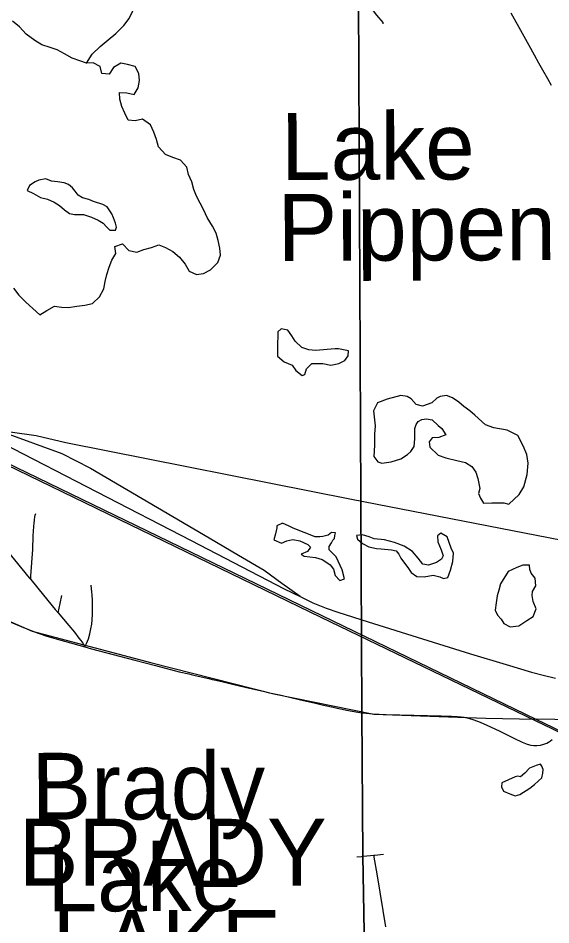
# Model space of a CAD drawing. Extents: x 0 to 34, y 0 to 22.
# Drawn here: x 4.548 to 5.303, y 14.669 to 15.953 of the extents above; entities that cross this region are included whole.
import ezdxf

# ---------------------------------------------------------------- set-up
doc = ezdxf.new("R2010")
doc.units = 0
for name, color, linetype in [('GM_X_Corporation', 7, 'Continuous'), ('GM_X_Corporation_Text', 7, 'Continuous'), ('GM_X_County_Road', 7, 'Continuous'), ('GM_X_Major_Lake', 7, 'Continuous'), ('GM_X_Major_Lake_Text', 7, 'Continuous'), ('GM_X_Minor_Lake', 7, 'Continuous'), ('GM_X_Minor_River', 7, 'Continuous'), ('GM_X_Rail_Line', 7, 'Continuous'), ('GM_X_Township_Road', 7, 'Continuous')]:
    doc.layers.add(name, color=color, linetype=linetype)

msp = doc.modelspace()

# ---------------------------------------------------------------- linework, layer by layer
at = {"layer": 'GM_X_Corporation'}
for points in [[(2.1, 14.1), (5.0398, 14.1), (5.0411, 14.425), (5.0381, 14.4922), (5.0378, 14.5635), (5.0395, 14.6051), (5.0366, 14.7668), (5.0353, 14.97), (5.0288, 16.3849), (5.0258, 16.7286), (5.0235, 17.4989), (5.0235, 17.5004), (5.0224, 17.5004), (4.9697, 17.5009), (4.8689, 17.5017), (4.8462, 17.5018), (4.8313, 17.5017), (4.8033, 17.5014), (4.7857, 17.5004), (4.7764, 17.4996), (4.7708, 17.4988), (4.7665, 17.4977), (4.718, 17.4962), (3.7119, 17.4934)], [(5.0288, 16.3849), (5.0353, 14.97), (5.0366, 14.7668), (5.0395, 14.6051), (5.0378, 14.5635), (5.0381, 14.4922), (5.0411, 14.425), (5.0398, 14.1), (8.9, 14.1)]]:
    msp.add_lwpolyline(points, dxfattribs=at)
at = {"layer": 'GM_X_County_Road'}
for points in [[(5.3042, 15.858), (5.2988, 15.8674), (5.2917, 15.8798), (5.2862, 15.8895), (5.28, 15.901), (5.2725, 15.9146), (5.2632, 15.9313), (5.247, 15.9603)], [(4.4651, 15.2783), (4.4794, 15.2608), (4.4944, 15.2435), (4.5133, 15.2212), (4.5219, 15.2114), (4.5641, 15.1605), (4.5661, 15.158)], [(4.5661, 15.158), (4.584, 15.1358), (4.6008, 15.1158), (4.605, 15.1108)], [(4.605, 15.1108), (4.6199, 15.0929), (4.6281, 15.0835), (4.6344, 15.0753), (4.6372, 15.0718), (4.6386, 15.0698), (4.6398, 15.0679), (4.6426, 15.0628)], [(4.5348, 15.0992), (4.5469, 15.0939), (4.5584, 15.0892), (4.5667, 15.086), (4.5701, 15.0846), (4.589, 15.078), (4.6056, 15.073), (4.6426, 15.0628)], [(4.6426, 15.0628), (4.6523, 15.0601), (4.7136, 15.0439), (4.7431, 15.0363), (4.7767, 15.0275), (4.79, 15.0244), (4.7936, 15.0236), (4.799, 15.0223), (4.8183, 15.0178), (4.8231, 15.0167), (4.8261, 15.0159), (4.8369, 15.0135), (4.8538, 15.0096), (4.8763, 15.0045), (4.8956, 14.9999), (4.9047, 14.9978), (4.9211, 14.9942), (4.9465, 14.9884), (4.9695, 14.9831), (4.981, 14.9804), (4.9949, 14.9773), (5.0003, 14.9761), (5.0076, 14.9746), (5.0137, 14.9733), (5.0295, 14.9703), (5.0355, 14.9694)], [(5.0355, 14.9694), (5.0374, 14.9692), (5.0504, 14.968), (5.0699, 14.9671), (5.1088, 14.9662), (5.1479, 14.9651), (5.1622, 14.9648), (5.171, 14.9642), (5.1761, 14.9636), (5.1802, 14.963), (5.1864, 14.9617), (5.1942, 14.9594), (5.203, 14.956), (5.2127, 14.9518), (5.224, 14.9466), (5.2307, 14.9433), (5.2507, 14.9333), (5.2625, 14.9277), (5.2694, 14.9251), (5.2747, 14.9237), (5.2789, 14.9232), (5.2831, 14.9231), (5.2885, 14.9236), (5.2932, 14.9248), (5.2977, 14.9266), (5.2999, 14.9277), (5.3027, 14.9295), (5.3052, 14.9316)]]:
    msp.add_lwpolyline(points, dxfattribs=at)
at = {"layer": 'GM_X_Major_Lake'}
msp.add_line((4.6134, 15.72), (4.6039, 15.7214), dxfattribs=at)
for points in [[(4.801, 15.5902), (4.8108, 15.5914), (4.821, 15.5968), (4.8315, 15.6072), (4.8352, 15.6178), (4.834, 15.6277), (4.8317, 15.6383), (4.8289, 15.6485), (4.8235, 15.6587), (4.8163, 15.6707), (4.8116, 15.6813), (4.8009, 15.701), (4.7974, 15.7108), (4.7943, 15.7214), (4.7897, 15.732), (4.7873, 15.7422), (4.7785, 15.752), (4.7675, 15.7557), (4.7573, 15.7602), (4.747, 15.7711), (4.7442, 15.7813), (4.7404, 15.7919), (4.7357, 15.8021), (4.7247, 15.81), (4.7141, 15.8076), (4.7043, 15.8087), (4.6993, 15.8185), (4.695, 15.8283), (4.6923, 15.8385), (4.6919, 15.848), (4.7021, 15.8477), (4.7127, 15.8451), (4.7183, 15.8547), (4.7205, 15.8649), (4.7193, 15.8748), (4.7139, 15.8846), (4.7033, 15.8875), (4.6938, 15.8894), (4.6836, 15.8832), (4.6773, 15.8737), (4.6671, 15.8747), (4.6643, 15.8846), (4.6548, 15.8902), (4.645, 15.8897), (4.6355, 15.8927), (4.6249, 15.8964), (4.6142, 15.9028), (4.6036, 15.9084), (4.5937, 15.9117), (4.5819, 15.9154), (4.5721, 15.9218), (4.5595, 15.9308), (4.55, 15.9409), (4.5404, 15.9488)], [(4.6039, 15.7214), (4.5956, 15.7225), (4.5876, 15.7255), (4.5778, 15.7239), (4.5725, 15.7216), (4.5646, 15.7162), (4.5609, 15.7093), (4.57, 15.7049), (4.5799, 15.6992), (4.5897, 15.6967), (4.5992, 15.6926), (4.6068, 15.6881), (4.6141, 15.6817), (4.6209, 15.6768), (4.6281, 15.6753), (4.641, 15.6751), (4.6524, 15.6714), (4.6619, 15.6673), (4.6687, 15.6631), (4.6733, 15.6579), (4.6782, 15.653), (4.6862, 15.653), (4.6877, 15.6572), (4.6861, 15.6629), (4.6834, 15.6705), (4.6811, 15.6761), (4.6746, 15.6859), (4.6685, 15.6893), (4.6552, 15.6938), (4.6484, 15.6964), (4.6393, 15.6989), (4.6332, 15.7027), (4.629, 15.708), (4.6252, 15.7129), (4.6195, 15.7178), (4.6134, 15.72)], [(4.5419, 15.5708), (4.5491, 15.561), (4.5594, 15.5508), (4.569, 15.5422), (4.5789, 15.5331), (4.5891, 15.5393), (4.5996, 15.5454), (4.6098, 15.544), (4.6197, 15.5433), (4.6314, 15.5453), (4.6427, 15.5469), (4.6537, 15.5493), (4.6638, 15.5584), (4.6698, 15.5699), (4.6716, 15.5801), (4.6742, 15.59), (4.6771, 15.6006), (4.6812, 15.6105), (4.6865, 15.6201), (4.6852, 15.6299), (4.6962, 15.6338), (4.705, 15.624), (4.7163, 15.6218), (4.7262, 15.6257), (4.7371, 15.6284), (4.7477, 15.6323), (4.7572, 15.6286), (4.7674, 15.623), (4.777, 15.6147), (4.785, 15.6049), (4.7907, 15.5951), (4.801, 15.5902)]]:
    msp.add_lwpolyline(points, dxfattribs=at)
at = {"layer": 'GM_X_Minor_Lake'}
for p, q in [((4.9975, 15.4848), (4.9695, 15.4827)), ((5.1995, 15.3013), (5.2027, 15.2873)), ((4.9693, 15.2188), (4.9382, 15.2307)), ((5.0906, 15.1882), (5.1017, 15.1739)), ((5.2295, 15.1431), (5.2273, 15.1351)), ((5.2524, 14.8789), (5.2339, 14.87))]:
    msp.add_line(p, q, dxfattribs=at)
for points in [[(4.9695, 15.4827), (4.96, 15.4834), (4.9502, 15.4867), (4.941, 15.4958), (4.936, 15.5033), (4.9307, 15.5112), (4.9208, 15.5134), (4.9163, 15.5092), (4.9157, 15.4865), (4.9158, 15.4747), (4.9253, 15.4664), (4.9364, 15.462), (4.9417, 15.4544), (4.9509, 15.4473), (4.9546, 15.4485), (4.9568, 15.4568), (4.9644, 15.4641), (4.9799, 15.4642), (4.9912, 15.4616), (5.0026, 15.464), (5.0113, 15.4683), (5.0161, 15.4751), (5.0164, 15.4819), (5.0024, 15.4849), (4.9975, 15.4848)], [(5.2027, 15.2873), (5.2008, 15.2801), (5.2035, 15.2733), (5.2077, 15.2665), (5.2195, 15.267), (5.2365, 15.2667), (5.2437, 15.2649), (5.2584, 15.2787), (5.2651, 15.2893), (5.2695, 15.3068), (5.2709, 15.3231), (5.2693, 15.3353), (5.2639, 15.3477), (5.2562, 15.3621), (5.2414, 15.3699), (5.2224, 15.3732), (5.2107, 15.3773), (5.1954, 15.3908), (5.1886, 15.3972), (5.1798, 15.4032), (5.1726, 15.4092), (5.1638, 15.4156), (5.1555, 15.4189), (5.1464, 15.4174), (5.1415, 15.415), (5.1344, 15.4082), (5.1215, 15.4035), (5.1124, 15.4061), (5.1052, 15.414), (5.0995, 15.4174), (5.0904, 15.4188), (5.0711, 15.4137), (5.0575, 15.4083), (5.0519, 15.3973), (5.054, 15.3757), (5.0533, 15.3639), (5.0534, 15.3487), (5.0524, 15.3324), (5.0578, 15.3249), (5.0639, 15.323), (5.0771, 15.325), (5.0907, 15.3293), (5.1001, 15.3351), (5.105, 15.3397), (5.1095, 15.3465), (5.1105, 15.3575), (5.1105, 15.3644), (5.1104, 15.3723), (5.1123, 15.3776), (5.1153, 15.3818), (5.1202, 15.3849), (5.127, 15.3857), (5.1349, 15.3843), (5.1433, 15.3764), (5.1486, 15.3722), (5.1544, 15.3632), (5.1446, 15.3593), (5.1351, 15.3589), (5.1306, 15.3531), (5.1318, 15.3456), (5.1436, 15.3343), (5.1543, 15.3306), (5.1698, 15.3269), (5.1823, 15.324), (5.1911, 15.3183), (5.1968, 15.31), (5.1995, 15.3013)], [(4.9382, 15.2307), (4.9325, 15.2337), (4.923, 15.2381), (4.915, 15.2343), (4.9147, 15.2316), (4.9129, 15.2229), (4.9107, 15.2145), (4.9217, 15.2097), (4.9292, 15.2132), (4.9375, 15.2147), (4.9474, 15.2129), (4.9588, 15.2077), (4.9626, 15.2039), (4.9585, 15.1978), (4.9494, 15.1943), (4.9536, 15.1913), (4.9699, 15.1892), (4.979, 15.1866), (4.9859, 15.1821), (4.9904, 15.1791), (4.995, 15.1727), (4.9977, 15.164), (5.0042, 15.1569), (5.0106, 15.1592), (5.0075, 15.172), (4.999, 15.1902), (4.9891, 15.2003), (4.9891, 15.2049), (4.9925, 15.2099), (4.9943, 15.2137), (4.9966, 15.2163), (4.9973, 15.2205), (4.998, 15.2243), (4.9923, 15.2246), (4.9874, 15.2212), (4.9803, 15.2189), (4.9757, 15.2188), (4.9693, 15.2188)], [(5.1017, 15.1739), (5.1052, 15.1679), (5.1132, 15.1626), (5.1238, 15.162), (5.1366, 15.1643), (5.1457, 15.1621), (5.1511, 15.1595), (5.1571, 15.1611), (5.1612, 15.1714), (5.1641, 15.1839), (5.1652, 15.1953), (5.1621, 15.2025), (5.1563, 15.2187), (5.1475, 15.2236), (5.1426, 15.2201), (5.1431, 15.2114), (5.1477, 15.2001), (5.1508, 15.1918), (5.1482, 15.1868), (5.141, 15.1822), (5.1297, 15.1783), (5.1218, 15.1798), (5.1152, 15.1884), (5.1072, 15.1979), (5.0954, 15.2053), (5.0814, 15.2105), (5.0674, 15.2142), (5.053, 15.2156), (5.0457, 15.2186), (5.0363, 15.2216), (5.0279, 15.2204), (5.0291, 15.2151), (5.0364, 15.2094), (5.0451, 15.2046), (5.0561, 15.202), (5.0629, 15.2017), (5.0773, 15.2003), (5.0838, 15.1988), (5.0876, 15.1943), (5.0906, 15.1882)], [(5.2273, 15.1351), (5.2259, 15.1252), (5.2241, 15.115), (5.2275, 15.1078), (5.2329, 15.1018), (5.2367, 15.0961), (5.2455, 15.0912), (5.2579, 15.0925), (5.2692, 15.1001), (5.2779, 15.1059), (5.2823, 15.1165), (5.2781, 15.1271), (5.2769, 15.1355), (5.2772, 15.1412), (5.2817, 15.1492), (5.2809, 15.1601), (5.2755, 15.1673), (5.2736, 15.1722), (5.2728, 15.1787), (5.2637, 15.1786), (5.255, 15.1751), (5.2429, 15.1693), (5.2317, 15.1522), (5.2295, 15.1431)], [(5.2339, 14.87), (5.2332, 14.8644), (5.2359, 14.8583), (5.245, 14.8546), (5.2526, 14.852), (5.2594, 14.8536), (5.2733, 14.8628), (5.2801, 14.8678), (5.2903, 14.8773), (5.2917, 14.8838), (5.2924, 14.8891), (5.2905, 14.894), (5.2886, 14.8966), (5.2822, 14.8947), (5.2727, 14.8912), (5.2664, 14.884), (5.26, 14.8786), (5.2562, 14.8797), (5.2524, 14.8789)]]:
    msp.add_lwpolyline(points, dxfattribs=at)
at = {"layer": 'GM_X_Minor_River'}
for points in [[(4.9645, 16.0784), (4.9767, 16.058), (4.9836, 16.0478), (4.9845, 16.038), (4.9921, 16.0282), (5.0024, 16.0184), (5.0116, 16.0082), (5.0222, 15.9981), (5.0295, 15.9875), (5.0375, 15.9777), (5.0486, 15.9672), (5.0562, 15.9574), (5.065, 15.9472), (5.065, 15.9453)], [(4.645, 15.8897), (4.6532, 15.9023), (4.6645, 15.913), (4.6761, 15.9226), (4.6867, 15.9314), (4.6979, 15.9428), (4.7058, 15.9528), (4.7106, 15.9638)]]:
    msp.add_lwpolyline(points, dxfattribs=at)
at = {"layer": 'GM_X_Rail_Line'}
for points in [[(6.8117, 14.2126), (6.7279, 14.2533), (6.3597, 14.4329), (6.2736, 14.4747), (5.6829, 14.7631), (5.3058, 14.9462), (5.2814, 14.958), (4.9779, 15.1046), (4.4205, 15.3745)], [(6.8127, 14.2147), (6.7289, 14.2554), (6.3608, 14.435), (6.2746, 14.4768), (5.684, 14.7652), (5.3068, 14.9483), (5.2824, 14.9601), (4.9789, 15.1067), (4.4214, 15.3767)], [(4.5188, 15.3705), (4.5246, 15.3679), (4.6101, 15.3367), (4.6509, 15.316), (4.8188, 15.217), (4.8605, 15.1928), (4.8971, 15.1712), (4.9221, 15.1532), (4.9478, 15.1346)], [(4.537, 15.3672), (4.5736, 15.3621), (4.6157, 15.3522), (5.0206, 15.272), (5.3364, 15.2108), (5.4679, 15.1911), (5.5237, 15.1833), (5.573, 15.1781), (5.6211, 15.1758), (5.6624, 15.1766), (5.704, 15.1802), (5.7573, 15.1883), (5.8023, 15.1965), (5.9026, 15.2069), (6.0592, 15.2263), (6.2427, 15.2569), (6.4412, 15.2812)], [(4.5262, 15.3513), (4.7934, 15.2133), (4.9254, 15.1452), (4.948, 15.1341), (4.966, 15.1252), (4.985, 15.1177), (5.0011, 15.1117), (5.0441, 15.0984), (5.1212, 15.0744), (5.1892, 15.0529), (5.2397, 15.0378), (5.2758, 15.0269), (5.2921, 15.0227), (5.31, 15.0185)], [(3.1616, 14.8692), (3.5915, 15.0597), (3.6949, 15.1071), (3.7867, 15.1408), (3.9605, 15.1904), (4.0114, 15.1928), (4.2869, 15.2006), (4.3333, 15.1875), (4.5683, 15.0852), (4.7376, 15.04), (4.9105, 14.9964), (5.0522, 14.9674), (5.2111, 14.9619), (5.2822, 14.9606)], [(7.7906, 14.1), (7.7891, 14.1611), (7.792, 14.368), (7.7915, 14.4601), (7.677, 14.4615), (7.605, 14.4663), (7.4966, 14.4734), (7.0511, 14.4887), (6.6677, 14.502), (6.4516, 14.5087), (6.0517, 14.9336), (5.3617, 14.959), (5.2822, 14.9606)]]:
    msp.add_lwpolyline(points, dxfattribs=at)
at = {"layer": 'GM_X_Township_Road'}
for points in [[(4.5661, 15.158), (4.5665, 15.1635), (4.5689, 15.2009), (4.5697, 15.22), (4.5707, 15.2335), (4.571, 15.2381), (4.5715, 15.2421), (4.5721, 15.2469), (4.5725, 15.2495), (4.5732, 15.2518)], [(4.6426, 15.0628), (4.6451, 15.0677), (4.6465, 15.0708), (4.6479, 15.0744), (4.6497, 15.0812), (4.6515, 15.0884), (4.6525, 15.0948), (4.6532, 15.101), (4.6538, 15.1092), (4.6538, 15.1197), (4.6536, 15.1284), (4.6532, 15.1364), (4.6529, 15.1401), (4.6518, 15.1503)], [(4.605, 15.1108), (4.6078, 15.1243), (4.6102, 15.1356)], [(5.0378, 14.7663), (5.0525, 14.7677), (5.0537, 14.7679), (5.0661, 14.7691)], [(5.0282, 14.7652), (5.035, 14.7661), (5.0368, 14.7662), (5.0378, 14.7663)], [(5.0693, 14.6661), (5.0573, 14.7385), (5.0525, 14.7677)]]:
    msp.add_lwpolyline(points, dxfattribs=at)

# ---------------------------------------------------------------- texts
at = {"layer": 'GM_X_Corporation_Text'}
for s, p in [('BRADY', (4.5492, 14.7246)), ('LAKE', (4.5967, 14.5952))]:
    msp.add_text(s, height=0.0947, rotation=0, dxfattribs=at).set_placement(p)
at = {"layer": 'GM_X_Major_Lake_Text'}
for s, height, rotation, p in [('Lake', 0.09474, 0.1754, (4.9208, 15.7241)), ('Pippen', 0.09474, 0.175, (4.916, 15.6094)), ('Brady', 0.09475, 0.1785, (4.5674, 14.8179)), ('Lake', 0.09475, 0.1792, (4.5898, 14.688))]:
    msp.add_text(s, height=height, rotation=rotation, dxfattribs=at).set_placement(p)

doc.saveas('drawing.dxf')
